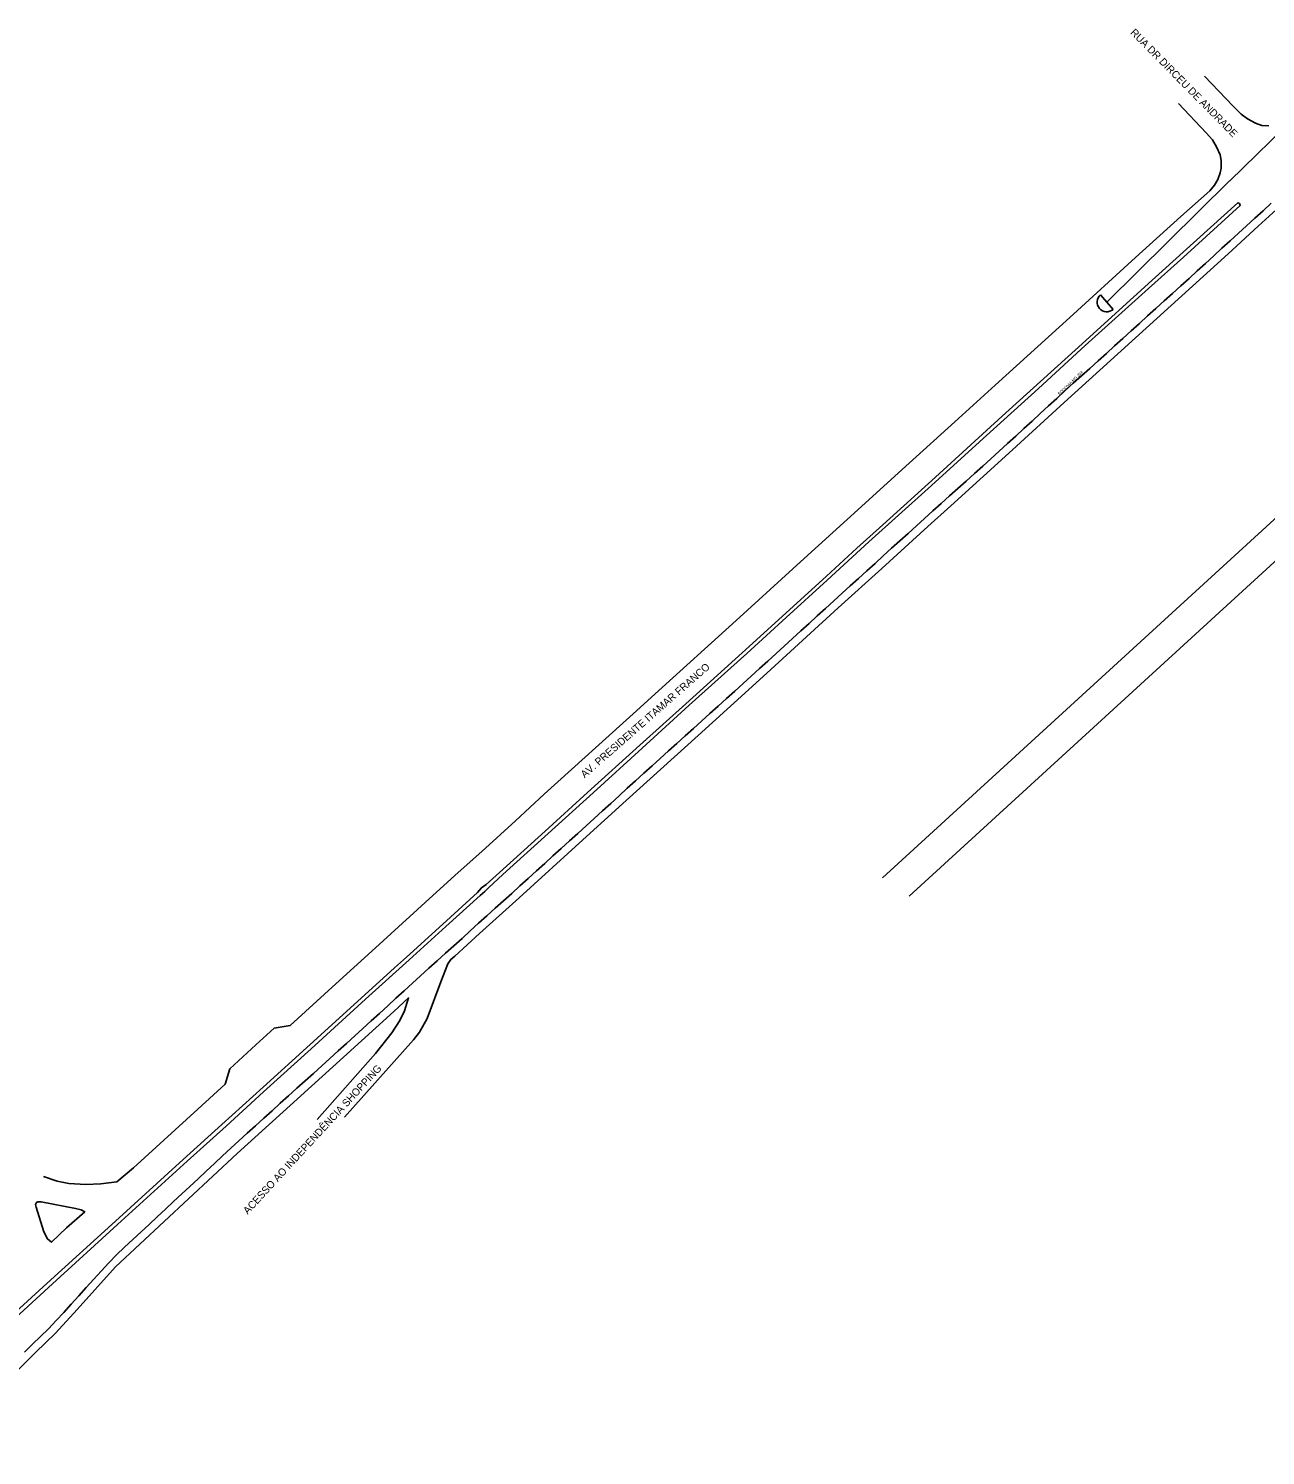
# Model space of a CAD drawing. Extents: x 656692 to 673945, y 7585994 to 7599066.
# Drawn here: x 666793 to 667885, y 7588952 to 7590211 of the extents above; entities that cross this region are included whole.
import ezdxf

# ---------------------------------------------------------------- set-up
doc = ezdxf.new("R2010")
doc.units = 0
for name, color, linetype in [('LOGRADOURO', 7, 'Continuous'), ('LOGRADOURO_TEXTO', 7, 'Continuous'), ('TUBO_PEAD_GN_125', 7, 'Continuous'), ('TUBO_PEAD_GN_63', 7, 'Continuous')]:
    doc.layers.add(name, color=color, linetype=linetype)

msp = doc.modelspace()

# ---------------------------------------------------------------- linework, layer by layer
at = {"layer": 'LOGRADOURO'}
for p, q in [((668046, 7589919.1), (667546.8, 7589462.1)), ((668067.1, 7589900.7), (667570.2, 7589445.9)), ((667072, 7589250.9), (667133, 7589319.2))]:
    msp.add_line(p, q, dxfattribs=at)
for points in [[(667887.6, 7590125.4), (667881.4, 7590125.8), (667875.8, 7590127.8), (667868.6, 7590131.7), (667863.2, 7590135.8), (667856, 7590142.9), (667830.7, 7590169.3)], [(667807.7, 7590145.2), (667832.2, 7590119.3), (667837.7, 7590113.2), (667841.5, 7590106.9), (667844.7, 7590099.8), (667845.4, 7590094.8), (667845.4, 7590088.2), (667844.6, 7590084), (667842.6, 7590078.1), (667839.6, 7590073.1), (667835.4, 7590068.1), (667810, 7590045.4), (667770, 7590009.2), (667711.9, 7589956.4), (667646.1, 7589896.6), (667610.6, 7589864.4), (667570.1, 7589827.7), (667515.6, 7589778.2), (667477.5, 7589743.6), (667417.7, 7589689), (667346.1, 7589624.2), (667329.8, 7589609.4), (667248.3, 7589535.8), (667222.9, 7589512.2), (667193.2, 7589485.2), (667172.5, 7589466.6), (667150, 7589446.3), (667099.5, 7589400.3), (667061.1, 7589365.4), (667024.1, 7589331.8), (667010.1, 7589329.3), (666994, 7589314.6), (666970.9, 7589293.4), (666966.9, 7589280), (666942.7, 7589257.9), (666886, 7589206.2), (666871.2, 7589193.8), (666857.1, 7589192), (666844, 7589191.4), (666829, 7589192.3), (666818.5, 7589194.4), (666806.7, 7589198.4)], [(667907.1, 7590063.5), (667878.1, 7590036.9), (667851.7, 7590012.5), (667707.1, 7589881.3), (667661.5, 7589839.5), (667607, 7589790.2), (667586.8, 7589772), (667546.1, 7589735), (667507.7, 7589700.1), (667448.1, 7589645.8), (667425.2, 7589624.9), (667384, 7589587.7), (667320.5, 7589530.3), (667282.4, 7589495.4), (667226.1, 7589444.4), (667191.3, 7589412.9), (667169.3, 7589392.9), (667165.8, 7589390), (667163.3, 7589386.1), (667161.1, 7589380.7), (667157.2, 7589370.2), (667145, 7589337.8), (667138.4, 7589325.9), (667133, 7589319.2)], [(666754, 7589053.6), (666809.8, 7589104.4), (666870.2, 7589159), (666929.9, 7589213.4), (666963.9, 7589244.4), (667000.5, 7589277.4), (667041.8, 7589314.9), (667086.7, 7589355.8), (667116.1, 7589382.6), (667126.8, 7589392.1), (667158.9, 7589421.2), (667189.5, 7589449), (667192.9, 7589453.3), (667197.2, 7589456.2), (667208.9, 7589466.6), (667249.1, 7589503.2), (667286.6, 7589537.4), (667332.6, 7589578.9), (667373.2, 7589615.4), (667423, 7589660.6), (667458.1, 7589692.7), (667497.2, 7589728.2), (667524.2, 7589752.9), (667547.1, 7589773.5), (667593.6, 7589815.6), (667652.4, 7589869.2), (667722.8, 7589933.1), (667781.5, 7589986.3), (667812, 7590014), (667860.2, 7590057.6), (667861.7, 7590056.8), (667862.3, 7590055.3), (667812.1, 7590009.7), (667781.4, 7589982), (667725.6, 7589931.5), (667684.3, 7589893.6), (667638.6, 7589852.3), (667586.9, 7589805.4), (667534.8, 7589758.4), (667497.9, 7589724.6), (667461.7, 7589691.6), (667427, 7589659.9), (667376.3, 7589614.2), (667334.6, 7589576.4), (667291.4, 7589536.9), (667251.9, 7589501), (667211.8, 7589465), (667199.4, 7589453.6), (667195.9, 7589449.8), (667191.7, 7589446.5), (667161.4, 7589419.2), (667129.3, 7589389.7), (667090.5, 7589355), (667042.8, 7589311.2), (667000.7, 7589273.1), (666967.7, 7589242.9), (666933.3, 7589211.9), (666872, 7589156.2), (666814.6, 7589103.9), (666760, 7589054.2)], [(666764.2, 7588985), (666757.2, 7588979.5), (666730.6, 7588955.7), (666726.2, 7588952.8), (666723.7, 7588952.4), (666722.6, 7588952.7), (666731.8, 7588967.9), (666743.8, 7588985.8), (666750.7, 7588993.8), (666761.8, 7589006.3), (666799.6, 7589043.2), (666817.3, 7589060.3), (666836.4, 7589081.1), (666870.1, 7589118.8), (666977.3, 7589218.7), (667033.5, 7589269.7), (667071.3, 7589303.7), (667115.5, 7589344.1), (667128.7, 7589356.1), (667125, 7589344.8), (667120.8, 7589336.1), (667114, 7589325.3), (667099.5, 7589306.9), (667048, 7589248.7)], [(666800.1, 7589171.5), (666799.6, 7589173.8), (666800.5, 7589175.6), (666801.6, 7589176.3), (666804.4, 7589176.3), (666834.9, 7589170.4), (666839.7, 7589169), (666843, 7589167.4), (666827, 7589153.1), (666813.6, 7589140.6), (666810, 7589143.5), (666807, 7589149.6), (666800.1, 7589171.5)]]:
    msp.add_lwpolyline(points, dxfattribs=at)
at = {"layer": 'TUBO_PEAD_GN_125'}
msp.add_lwpolyline([(667889.7, 7590057.3), (667882.4, 7590050.6), (667875.2, 7590044), (667867.9, 7590037.3), (667860.7, 7590030.7), (667853.4, 7590024), (667846.2, 7590017.4), (667838.9, 7590010.7), (667831.7, 7590004.1), (667824.4, 7589997.5), (667817.1, 7589990.8), (667809.8, 7589984.2), (667802.5, 7589977.6), (667795.2, 7589971), (667787.9, 7589964.4), (667780.6, 7589957.8), (667773.3, 7589951.2), (667766, 7589944.5), (667758.8, 7589937.9), (667751.5, 7589931.3), (667744.2, 7589924.7), (667736.9, 7589918.1), (667729.6, 7589911.5), (667722.3, 7589904.9), (667715, 7589898.3), (667707.7, 7589891.6), (667700.5, 7589885), (667693.2, 7589878.4), (667685.9, 7589871.7), (667678.7, 7589865), (667671.4, 7589858.4), (667664.2, 7589851.7), (667656.9, 7589845.1), (667649.7, 7589838.5), (667642.4, 7589831.8), (667635.1, 7589825.2), (667627.8, 7589818.6), (667620.5, 7589812.1), (667613.1, 7589805.5), (667605.8, 7589798.9), (667598.5, 7589792.3), (667591.2, 7589785.7), (667583.9, 7589779.1), (667576.6, 7589772.5), (667569.3, 7589765.9), (667562, 7589759.3), (667554.7, 7589752.7), (667547.4, 7589746.1), (667540.2, 7589739.4), (667532.9, 7589732.8), (667525.6, 7589726.2), (667518.3, 7589719.6), (667511, 7589713), (667503.7, 7589706.3), (667496.5, 7589699.7), (667489.2, 7589693.1), (667481.9, 7589686.4), (667474.7, 7589679.8), (667467.4, 7589673.2), (667460.1, 7589666.5), (667452.9, 7589659.9), (667445.6, 7589653.3), (667438.3, 7589646.6), (667431, 7589640), (667423.7, 7589633.4), (667416.4, 7589626.8), (667409.1, 7589620.2), (667401.8, 7589613.6), (667394.5, 7589607), (667387.2, 7589600.4), (667379.9, 7589593.8), (667372.6, 7589587.2), (667365.3, 7589580.6), (667358, 7589574), (667350.7, 7589567.4), (667343.4, 7589560.8), (667336.1, 7589554.2), (667328.8, 7589547.6), (667321.5, 7589541), (667314.3, 7589534.3), (667307, 7589527.7), (667299.7, 7589521.1), (667292.5, 7589514.4), (667285.2, 7589507.8), (667277.9, 7589501.2), (667270.6, 7589494.6), (667263.3, 7589487.9), (667256, 7589481.3), (667248.7, 7589474.7), (667241.4, 7589468.1), (667234.1, 7589461.5), (667226.9, 7589454.9), (667219.6, 7589448.3), (667212.3, 7589441.7), (667205, 7589435.1), (667197.7, 7589428.5), (667190.4, 7589421.9), (667183.1, 7589415.2), (667175.8, 7589408.6), (667168.5, 7589402), (667161.2, 7589395.4), (667153.9, 7589388.8), (667146.6, 7589382.2), (667139.3, 7589375.6), (667132, 7589369), (667124.7, 7589362.4), (667117.5, 7589355.7), (667110.2, 7589349.1), (667103, 7589342.4), (667095.7, 7589335.8), (667088.4, 7589329.2), (667081.2, 7589322.5), (667073.9, 7589315.9), (667066.6, 7589309.3), (667059.3, 7589302.7), (667052, 7589296.1), (667044.7, 7589289.5), (667037.3, 7589282.9), (667030, 7589276.3), (667022.7, 7589269.7), (667015.5, 7589263.1), (667008.2, 7589256.5), (667000.9, 7589249.9), (666993.6, 7589243.3), (666986.3, 7589236.6), (666979, 7589230), (666971.8, 7589223.4), (666964.6, 7589216.7), (666957.4, 7589209.9), (666950.2, 7589203.2), (666943, 7589196.5), (666935.8, 7589189.8), (666928.6, 7589183.1), (666921.4, 7589176.4), (666914.2, 7589169.7), (666907, 7589163), (666899.8, 7589156.3), (666892.6, 7589149.6), (666885.3, 7589142.9), (666878.1, 7589136.2), (666871, 7589129.4), (666864.1, 7589122.4), (666857.5, 7589115.1), (666850.9, 7589107.8), (666844.3, 7589100.5), (666837.7, 7589093.2), (666831, 7589085.9), (666824.4, 7589078.6), (666817.8, 7589071.4), (666811, 7589064.2), (666804, 7589057.3), (666796.9, 7589050.5), (666789.9, 7589043.6)], dxfattribs=at)
at = {"layer": 'TUBO_PEAD_GN_63'}
for p, q in [((667969.3, 7590190.4), (667853, 7590077)), ((667852.9, 7590077), (667744.6, 7589969.9)), ((667739, 7589976.4), (667750.1, 7589963.5))]:
    msp.add_line(p, q, dxfattribs=at)
for centre, radius, start, end in [((667855.2, 7590074.7), 3.28, 134.2646, 134.6649), ((667744.6, 7589969.9), 8.51, 130.8048, 310.8048)]:
    msp.add_arc(centre, radius, start, end, dxfattribs=at)

# ---------------------------------------------------------------- texts
at = {"layer": 'LOGRADOURO_TEXTO'}
for s, height, rotation, p in [('RUA DR DIRCEU DE ANDRADE', 6.562, 314.5592, (667764.9, 7590207.2)), ('RODOVIA MG 353', 2.461, 43.7892, (667703, 7589887.8)), ('AV. PRESIDENTE ITAMAR FRANCO', 6.562, 41.2693, (667284, 7589549.7)), ('ACESSO AO INDEPENDÊNCIA SHOPPING', 6.562, 47.3382, (666986.8, 7589164.7))]:
    msp.add_text(s, height=height, rotation=rotation, dxfattribs=at).set_placement(p)

doc.saveas('drawing.dxf')
